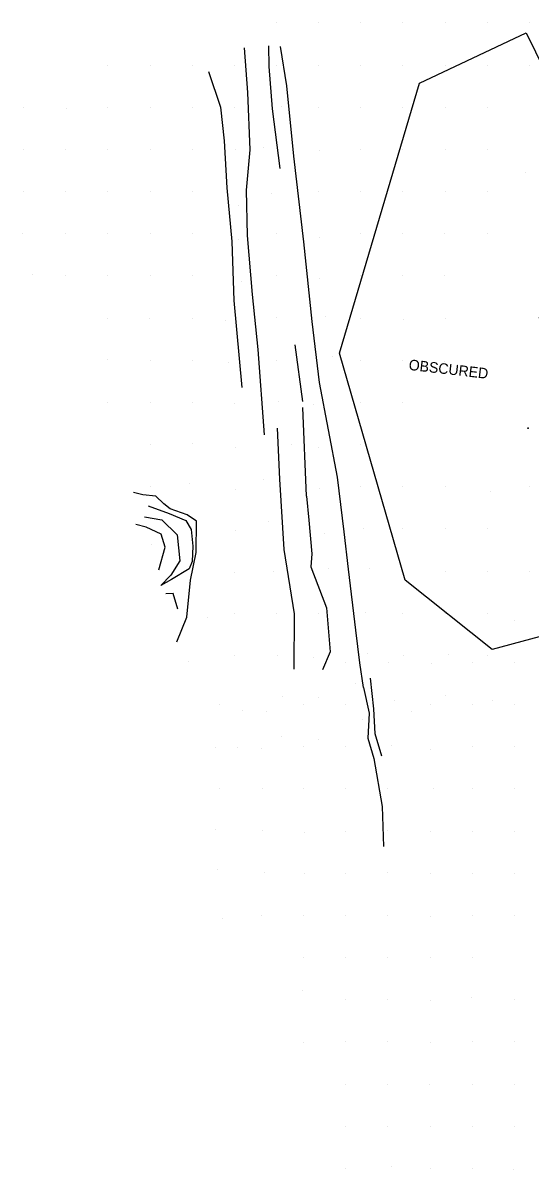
# Model space of a CAD drawing. Extents: x 524772 to 528246, y 273285 to 283088.
# Drawn here: x 526986.4 to 527059.7, y 275381.9 to 275547.6 of the extents above; entities that cross this region are included whole.
import ezdxf

# ---------------------------------------------------------------- set-up
doc = ezdxf.new("R2010")
doc.units = 0
for name, color, linetype in [('Exist DTM Regular Point CELL', 7, 'Continuous'), ('PH Exist DTM Breakline', 7, 'Continuous'), ('PH Exist DTM Obscure Area', 7, 'Continuous'), ('PH Exist DTM Obscure Area Text', 7, 'Continuous'), ('PH Exist DTM Point', 7, 'Continuous')]:
    doc.layers.add(name, color=color, linetype=linetype)

# ---------------------------------------------------------------- blocks, each defined once
blk = doc.blocks.new('EXIST DTM REGULAR POINT')
at = {"layer": 'Exist DTM Regular Point CELL'}
blk.add_lwpolyline([(0, 0.0015), (0, -0.0015), (0, 0), (0.0015, 0), (-0.0015, 0)], dxfattribs=at)
blk.add_circle((0, 0), 0.00119, dxfattribs=at)

msp = doc.modelspace()

# ---------------------------------------------------------------- linework, layer by layer
at = {"layer": 'PH Exist DTM Breakline'}
for points in [[(527018.38, 275543.99), (527018.87, 275537.57), (527019.21, 275529.24), (527018.68, 275523.41), (527018.78, 275516.88), (527019.52, 275508.34), (527020.32, 275500.4), (527021.27, 275488.04)], [(527021.89, 275544.31), (527021.91, 275541.3), (527022.41, 275535.17), (527023.54, 275526.56)], [(527035.61, 275451.51), (527035.1, 275455.1), (527034.51, 275459.82), (527033.47, 275468.66), (527032.85, 275474.04), (527031.85, 275481.95), (527029.28, 275495.64), (527028.18, 275504.43), (527027.01, 275515.97), (527025.54, 275528.33), (527024.52, 275538.51), (527023.64, 275544.18)], [(527013.2, 275540.61), (527014.95, 275535.42), (527015.48, 275530.54), (527015.87, 275523.76), (527016.56, 275515.99), (527016.89, 275507.46), (527018.01, 275494.92)], [(527025.67, 275501.08), (527026.79, 275492.86)], [(527027.38, 275479.2), (527026.86, 275492.03)], [(527023.14, 275489.04), (527023.48, 275481.66), (527024.11, 275471.5), (527025.58, 275462.17), (527025.56, 275454.16)], [(527008.63, 275458.12), (527010.08, 275461.72), (527010.62, 275467.05), (527011.42, 275471.05), (527011.49, 275475.59), (527010.12, 275476.49), (527007.66, 275477.36), (527006.76, 275478.08), (527005.6, 275479.19), (527003.73, 275479.38), (527002.35, 275479.71)], [(527027.38, 275479.2), (527027.73, 275475.71), (527028.17, 275470.84), (527027.99, 275468.96), (527030.25, 275463.03), (527030.8, 275456.67), (527029.7, 275454.09)], [(527004.48, 275477.81), (527007.54, 275476.7), (527009.92, 275475.69), (527010.71, 275474.37), (527010.94, 275471.97), (527010.85, 275469.74), (527010.39, 275468.71), (527007.85, 275467.17), (527006.33, 275466.29)], [(527003.97, 275476.19), (527006.46, 275475.78), (527008.69, 275473.6), (527009.07, 275469.83), (527007.76, 275467.77), (527006.33, 275466.29)], [(527006.02, 275468.53), (527006.94, 275471.81), (527006.37, 275473.72), (527004.19, 275474.69), (527002.7, 275475.09)], [(527008.77, 275462.88), (527008.12, 275465.11), (527007.02, 275465.05)], [(527038.27, 275441.59), (527037.32, 275444.83), (527037.1, 275448.44), (527036.66, 275452.88)], [(527035.61, 275451.51), (527036.45, 275447.84), (527036.25, 275444.23), (527037.12, 275441.25), (527038.34, 275434.31), (527038.51, 275428.57)]]:
    msp.add_lwpolyline(points, dxfattribs=at)
at = {"layer": 'PH Exist DTM Obscure Area'}
msp.add_lwpolyline([(527069.84, 275488.82), (527085.16, 275481.84), (527087.96, 275473.66), (527080.16, 275464.01), (527054.21, 275457.05), (527041.65, 275467.07), (527032.17, 275499.85), (527043.72, 275538.88), (527059.13, 275546.19), (527067.25, 275529.71), (527061.04, 275505.02), (527068.22, 275489.27), (527069.84, 275488.82)], dxfattribs=at)
at = {"layer": 'PH Exist DTM Point'}
for p, q in [((527023.04, 275547.61), (527023.04, 275547.61)), ((527029.13, 275547.61), (527029.13, 275547.61)), ((527035.23, 275547.61), (527035.23, 275547.61)), ((527041.32, 275547.61), (527041.32, 275547.61)), ((527047.42, 275547.61), (527047.42, 275547.61)), ((527053.52, 275547.61), (527053.52, 275547.61)), ((527059.61, 275547.61), (527059.61, 275547.61)), ((526998.65, 275541.51), (526998.65, 275541.51)), ((527004.75, 275541.51), (527004.75, 275541.51)), ((527010.84, 275541.51), (527010.84, 275541.51)), ((527016.94, 275541.51), (527016.94, 275541.51)), ((527023.04, 275541.51), (527023.04, 275541.51)), ((527029.13, 275541.51), (527029.13, 275541.51)), ((527035.23, 275541.51), (527035.23, 275541.51)), ((527041.32, 275541.51), (527041.32, 275541.51)), ((527047.42, 275541.51), (527047.42, 275541.51)), ((527053.52, 275541.51), (527053.52, 275541.51)), ((527059.61, 275541.51), (527059.61, 275541.51)), ((527023.81, 275535.54), (527023.81, 275535.54)), ((526986.46, 275535.42), (526986.46, 275535.42)), ((526992.67, 275535.3), (526992.67, 275535.3)), ((526998.65, 275535.42), (526998.65, 275535.42)), ((527004.75, 275535.4), (527004.75, 275535.4)), ((527010.86, 275535.42), (527010.86, 275535.42)), ((527016.96, 275535.41), (527016.96, 275535.41)), ((527029.13, 275535.42), (527029.13, 275535.42)), ((527035.23, 275535.42), (527035.23, 275535.42)), ((527041.32, 275535.42), (527041.32, 275535.42)), ((527047.44, 275535.41), (527047.44, 275535.41)), ((527053.52, 275535.42), (527053.52, 275535.42)), ((526986.46, 275529.31), (526986.46, 275529.31)), ((526992.56, 275529.32), (526992.56, 275529.32)), ((526998.65, 275529.32), (526998.65, 275529.32)), ((527004.75, 275529.32), (527004.75, 275529.32)), ((527010.84, 275529.32), (527010.84, 275529.32)), ((527017.11, 275529.37), (527017.11, 275529.37)), ((527021.21, 275529.6), (527021.21, 275529.6)), ((527029.19, 275529.13), (527029.19, 275529.13)), ((527035.23, 275529.32), (527035.23, 275529.32)), ((527041.32, 275529.32), (527041.32, 275529.32)), ((527047.47, 275529.27), (527047.47, 275529.27)), ((527053.52, 275529.32), (527053.52, 275529.32)), ((527059.07, 275525.93), (527059.07, 275525.93)), ((526986.46, 275523.22), (526986.46, 275523.22)), ((526992.56, 275523.22), (526992.56, 275523.22)), ((526998.65, 275523.22), (526998.65, 275523.22)), ((527004.75, 275523.22), (527004.75, 275523.22)), ((527010.84, 275523.22), (527010.84, 275523.22)), ((527022.35, 275523.02), (527022.35, 275523.02)), ((527029.13, 275523.24), (527029.13, 275523.24)), ((527035.23, 275523.22), (527035.23, 275523.22)), ((527041.32, 275523.22), (527041.32, 275523.22)), ((527047.42, 275523.22), (527047.42, 275523.22)), ((527053.52, 275523.22), (527053.52, 275523.22)), ((527017.53, 275521.21), (527017.53, 275521.21)), ((526986.37, 275517.23), (526986.37, 275517.23)), ((526992.56, 275517.13), (526992.56, 275517.13)), ((526998.65, 275517.13), (526998.65, 275517.13)), ((527004.77, 275517.12), (527004.77, 275517.12)), ((527010.84, 275517.13), (527010.84, 275517.13)), ((527017.61, 275516.24), (527017.61, 275516.24)), ((527023.04, 275517.13), (527023.04, 275517.13)), ((527029.3, 275516.56), (527029.3, 275516.56)), ((527035.23, 275517.13), (527035.23, 275517.13)), ((527041.32, 275517.13), (527041.32, 275517.13)), ((527047.41, 275517.14), (527047.41, 275517.14)), ((527053.52, 275517.13), (527053.52, 275517.13)), ((526987.77, 275511.17), (526987.77, 275511.17)), ((526992.56, 275511.03), (526992.56, 275511.03)), ((526998.65, 275511.03), (526998.65, 275511.03)), ((527004.75, 275511.03), (527004.75, 275511.03)), ((527010.84, 275511.03), (527010.84, 275511.03)), ((527023.04, 275511.03), (527023.04, 275511.03)), ((527029.24, 275510.68), (527029.24, 275510.68)), ((527035.23, 275511.03), (527035.23, 275511.03)), ((527041.32, 275511.03), (527041.32, 275511.03)), ((527047.4, 275511.04), (527047.4, 275511.04)), ((527018.03, 275510.26), (527018.03, 275510.26)), ((526998.65, 275504.94), (526998.65, 275504.94)), ((527004.74, 275504.95), (527004.74, 275504.95)), ((527010.83, 275504.92), (527010.83, 275504.92)), ((527015.71, 275504.62), (527015.71, 275504.62)), ((527023.01, 275505.01), (527023.01, 275505.01)), ((527030.12, 275505.15), (527030.12, 275505.15)), ((527035.23, 275504.94), (527035.23, 275504.94)), ((527041.38, 275504.74), (527041.38, 275504.74)), ((527047.42, 275504.94), (527047.42, 275504.94)), ((527031.09, 275499.34), (527031.09, 275499.34)), ((526998.56, 275498.88), (526998.56, 275498.88)), ((527004.76, 275498.85), (527004.76, 275498.85)), ((527010.84, 275498.84), (527010.84, 275498.84)), ((527016.03, 275498.57), (527016.03, 275498.57)), ((527023.04, 275498.84), (527023.04, 275498.84)), ((527035.23, 275498.84), (527035.23, 275498.84)), ((527041.32, 275498.84), (527041.32, 275498.84)), ((527047.28, 275498.7), (527047.28, 275498.7)), ((526998.65, 275492.74), (526998.65, 275492.74)), ((527004.75, 275492.74), (527004.75, 275492.74)), ((527010.85, 275492.77), (527010.85, 275492.77)), ((527016.96, 275492.66), (527016.96, 275492.66)), ((527023.39, 275492.91), (527023.39, 275492.91)), ((527035.23, 275492.74), (527035.23, 275492.74)), ((527041.32, 275492.74), (527041.32, 275492.74)), ((527028.39, 275492.42), (527028.39, 275492.42)), ((527004.77, 275486.64), (527004.77, 275486.64)), ((527010.94, 275486.78), (527010.94, 275486.78)), ((527017.07, 275486.21), (527017.07, 275486.21)), ((527025.2, 275486.63), (527025.2, 275486.63)), ((527029.18, 275486.17), (527029.18, 275486.17)), ((527035.23, 275486.65), (527035.23, 275486.65)), ((527010.49, 275481.02), (527010.49, 275481.02)), ((527021.23, 275481.61), (527021.23, 275481.61)), ((527004.76, 275480.56), (527004.76, 275480.56)), ((527017.05, 275480.17), (527017.05, 275480.17)), ((527029.24, 275480.3), (527029.24, 275480.3)), ((527035.23, 275480.55), (527035.23, 275480.55)), ((527041.32, 275480.55), (527041.32, 275480.55)), ((527047.43, 275480.59), (527047.43, 275480.59)), ((527054.04, 275479.85), (527054.04, 275479.85)), ((527059.68, 275480.56), (527059.68, 275480.56)), ((527021.9, 275475.46), (527021.9, 275475.46)), ((527035.6, 275474.57), (527035.6, 275474.57)), ((527041.32, 275474.46), (527041.32, 275474.46)), ((527047.42, 275474.46), (527047.42, 275474.46)), ((527053.52, 275474.46), (527053.52, 275474.46)), ((527017.05, 275474.18), (527017.05, 275474.18)), ((527029.96, 275473.82), (527029.96, 275473.82)), ((527004.94, 275472.14), (527004.94, 275472.14)), ((527016.99, 275468.2), (527016.99, 275468.2)), ((527022.68, 275468.25), (527022.68, 275468.25)), ((527030.61, 275468.67), (527030.61, 275468.67)), ((527036.52, 275468.76), (527036.52, 275468.76)), ((527041.32, 275468.36), (527041.32, 275468.36)), ((527047.42, 275468.36), (527047.42, 275468.36)), ((527053.52, 275468.36), (527053.52, 275468.36)), ((527059.63, 275468.36), (527059.63, 275468.36)), ((527013.02, 275461.69), (527013.02, 275461.69)), ((527016.95, 275462.22), (527016.95, 275462.22)), ((527023.04, 275462.26), (527023.04, 275462.26)), ((527029.12, 275462.26), (527029.12, 275462.26)), ((527035.89, 275462.43), (527035.89, 275462.43)), ((527041.32, 275462.26), (527041.32, 275462.26)), ((527047.42, 275462.26), (527047.42, 275462.26)), ((527053.52, 275462.26), (527053.52, 275462.26)), ((527057.44, 275461.26), (527057.44, 275461.26)), ((527016.95, 275456.13), (527016.95, 275456.13)), ((527023.15, 275456.2), (527023.15, 275456.2)), ((527036.17, 275456.45), (527036.17, 275456.45)), ((527041.38, 275456.15), (527041.38, 275456.15)), ((527047.96, 275456.32), (527047.96, 275456.32)), ((527053.52, 275456.17), (527053.52, 275456.17)), ((527010.25, 275455.33), (527010.25, 275455.33)), ((527028.37, 275455.94), (527028.37, 275455.94)), ((527033.05, 275455.17), (527033.05, 275455.17)), ((527039.22, 275455.19), (527039.22, 275455.19)), ((527045.49, 275454.97), (527045.49, 275454.97)), ((527051.34, 275455.17), (527051.34, 275455.17)), ((527057.44, 275455.17), (527057.44, 275455.17)), ((527034.47, 275452.12), (527034.47, 275452.12)), ((527023.84, 275450.28), (527023.84, 275450.28)), ((527029.13, 275450.07), (527029.13, 275450.07)), ((527040.11, 275449.6), (527040.11, 275449.6)), ((527047.47, 275450.39), (527047.47, 275450.39)), ((527054.29, 275449.65), (527054.29, 275449.65)), ((527014.78, 275449.01), (527014.78, 275449.01)), ((527018.17, 275448.15), (527018.17, 275448.15)), ((527021.58, 275448.11), (527021.58, 275448.11)), ((527026.96, 275449.07), (527026.96, 275449.07)), ((527033.06, 275449.07), (527033.06, 275449.07)), ((527042.52, 275448.12), (527042.52, 275448.12)), ((527045.25, 275449.07), (527045.25, 275449.07)), ((527051.34, 275449.07), (527051.34, 275449.07)), ((527057.44, 275449.07), (527057.44, 275449.07)), ((527035.41, 275446.94), (527035.41, 275446.94)), ((527023.82, 275444.44), (527023.82, 275444.44)), ((527014.25, 275442.82), (527014.25, 275442.82)), ((527017.43, 275442.86), (527017.43, 275442.86)), ((527026.96, 275442.98), (527026.96, 275442.98)), ((527029.13, 275443.98), (527029.13, 275443.98)), ((527033.04, 275442.97), (527033.04, 275442.97)), ((527039.61, 275443.18), (527039.61, 275443.18)), ((527051.34, 275442.97), (527051.34, 275442.97)), ((527057.44, 275442.97), (527057.44, 275442.97)), ((527020.93, 275442.65), (527020.93, 275442.65)), ((527045.36, 275442.59), (527045.36, 275442.59)), ((527014.78, 275436.91), (527014.78, 275436.91)), ((527021.07, 275436.94), (527021.07, 275436.94)), ((527026.96, 275436.88), (527026.96, 275436.88)), ((527033.05, 275436.88), (527033.05, 275436.88)), ((527039.11, 275436.9), (527039.11, 275436.9)), ((527045.8, 275436.99), (527045.8, 275436.99)), ((527051.34, 275436.88), (527051.34, 275436.88)), ((527057.44, 275436.88), (527057.44, 275436.88)), ((527014.22, 275431.02), (527014.22, 275431.02)), ((527021.09, 275430.85), (527021.09, 275430.85)), ((527027.02, 275430.59), (527027.02, 275430.59)), ((527033.05, 275430.78), (527033.05, 275430.78)), ((527039.13, 275430.87), (527039.13, 275430.87)), ((527045.31, 275430.73), (527045.31, 275430.73)), ((527051.34, 275430.78), (527051.34, 275430.78)), ((527057.44, 275430.78), (527057.44, 275430.78)), ((527014.57, 275425.15), (527014.57, 275425.15)), ((527021.26, 275424.77), (527021.26, 275424.77)), ((527027.02, 275424.71), (527027.02, 275424.71)), ((527033.05, 275424.69), (527033.05, 275424.69)), ((527039.12, 275424.73), (527039.12, 275424.73)), ((527045.27, 275424.61), (527045.27, 275424.61)), ((527051.34, 275424.69), (527051.34, 275424.69)), ((527057.44, 275424.69), (527057.44, 275424.69)), ((527015.29, 275418.17), (527015.29, 275418.17)), ((527020.87, 275418.58), (527020.87, 275418.58)), ((527026.94, 275418.63), (527026.94, 275418.63)), ((527033.05, 275418.59), (527033.05, 275418.59)), ((527039.15, 275418.59), (527039.15, 275418.59)), ((527045.32, 275418.46), (527045.32, 275418.46)), ((527051.34, 275418.59), (527051.34, 275418.59)), ((527057.44, 275418.59), (527057.44, 275418.59)), ((527026.97, 275412.56), (527026.97, 275412.56)), ((527033.05, 275412.49), (527033.05, 275412.49)), ((527039.15, 275412.49), (527039.15, 275412.49)), ((527045.25, 275412.48), (527045.25, 275412.48)), ((527051.41, 275412.47), (527051.41, 275412.47)), ((527026.86, 275407.77), (527026.86, 275407.77)), ((527033.05, 275406.4), (527033.05, 275406.4)), ((527039.15, 275406.4), (527039.15, 275406.4)), ((527051.27, 275406.65), (527051.27, 275406.65)), ((527057.44, 275406.4), (527057.44, 275406.4)), ((527045.28, 275406.27), (527045.28, 275406.27)), ((527026.9, 275400.28), (527026.9, 275400.28)), ((527033.05, 275400.3), (527033.05, 275400.3)), ((527039.15, 275400.3), (527039.15, 275400.3)), ((527045.26, 275400.26), (527045.26, 275400.26)), ((527051.34, 275400.3), (527051.34, 275400.3)), ((527057.44, 275400.3), (527057.44, 275400.3)), ((527033.05, 275394.21), (527033.05, 275394.21)), ((527039.15, 275394.21), (527039.15, 275394.21)), ((527045.24, 275394.2), (527045.24, 275394.2)), ((527051.34, 275394.2), (527051.34, 275394.2)), ((527057.44, 275394.21), (527057.44, 275394.21)), ((527033.05, 275388.11), (527033.05, 275388.11)), ((527039.15, 275388.11), (527039.15, 275388.11)), ((527045.25, 275388.11), (527045.25, 275388.11)), ((527051.34, 275388.11), (527051.34, 275388.11)), ((527057.44, 275388.11), (527057.44, 275388.11)), ((527033.05, 275382.01), (527033.05, 275382.01)), ((527039.62, 275382.26), (527039.62, 275382.26)), ((527045.25, 275382.01), (527045.25, 275382.01)), ((527051.34, 275382.01), (527051.34, 275382.01)), ((527057.37, 275381.91), (527057.37, 275381.91))]:
    msp.add_line(p, q, dxfattribs=at)

# ---------------------------------------------------------------- block references
at = {"layer": 'Exist DTM Regular Point CELL', "xscale": 38.1000762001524, "yscale": 38.1000762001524}
msp.add_blockref('EXIST DTM REGULAR POINT', (527059.43, 275489.03), dxfattribs=at)

# ---------------------------------------------------------------- texts
at = {"layer": 'PH Exist DTM Obscure Area Text'}
msp.add_text('OBSCURED', height=1.524, rotation=353.4693, dxfattribs=at).set_placement((527042.1, 275497.46))

doc.saveas('drawing.dxf')
